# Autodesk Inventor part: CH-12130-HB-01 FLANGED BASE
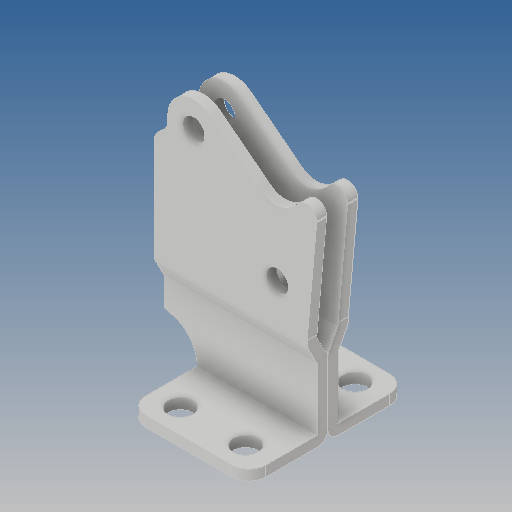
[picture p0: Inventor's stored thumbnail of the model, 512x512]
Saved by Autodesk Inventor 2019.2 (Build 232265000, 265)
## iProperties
Created: 2012-09
Part Number: CH-12130-HB-01 FLANGED BASE
Material: Ogólny
Document SubType Name: Modeling
Designer: CADENGINEERING4
Density: 1 g/cm^3
Appearance: Domyślna
Author: CADENGINEERING4
Revision Number: ÈÎºÎ
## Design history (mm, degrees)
feature "¾µÏò2"
feature "ÇÐ³ý-À­Éì5"
node "Bryła1"
node "Bryła2"
